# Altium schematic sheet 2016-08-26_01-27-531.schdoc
size 237 x 127 mm; SheetNumber: 1; SheetTotal: 1
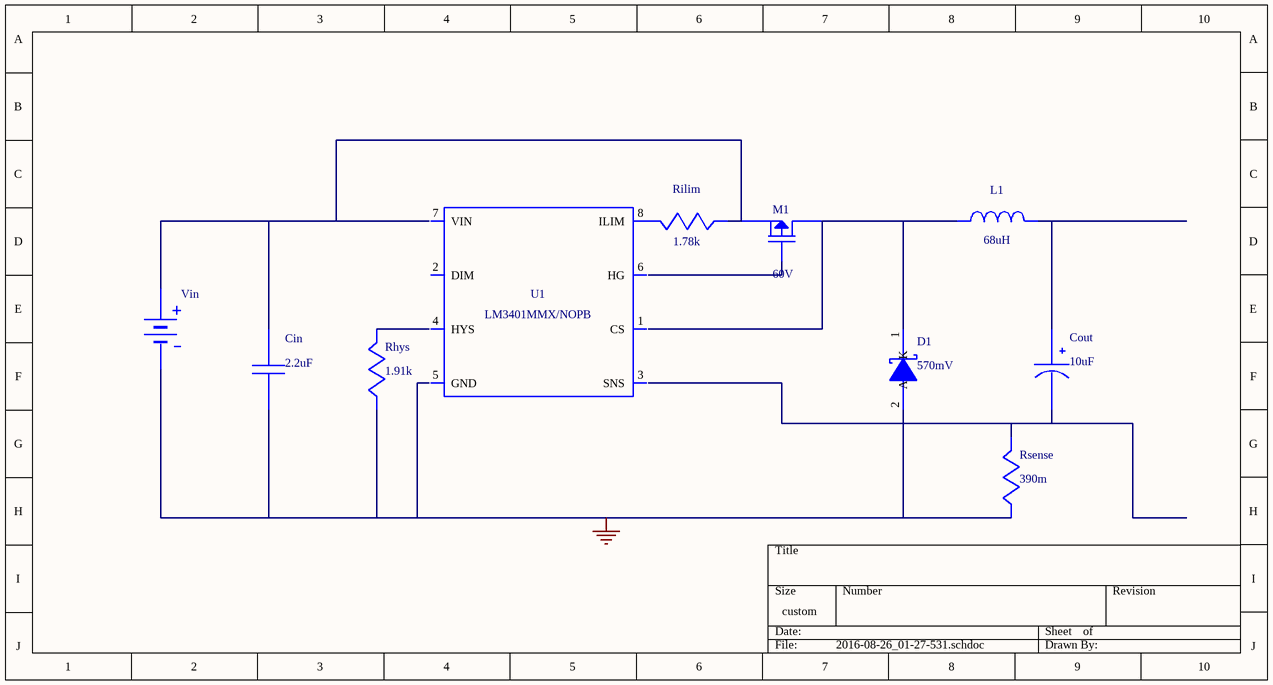
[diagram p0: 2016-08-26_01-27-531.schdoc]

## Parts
Cin  value 2.2uF  (hidden comment: GRM31CR71H225KA88L)
Cout  value 10uF  (hidden comment: UUD1V100MCL1GS)
D1  value 570mV  (hidden comment: PMEG6010CEH,115)
L1  value 68uH  (hidden comment: SRN6045-680M)
M1  value -60V  (hidden comment: FDC5614P)
Rhys  value 1.91k  (hidden comment: ERJ-6ENF1911V)
Rilim  value 1.78k  (hidden comment: ERJ-6ENF1781V)
Rsense  value 390m  (hidden comment: ERJ-8RQFR39V)
U1  LM3401MMX/NOPB
Vin  WB_BATTERY  (value not drawn)

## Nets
0: Cin.2 D1.2(A) Rhys.2 Rsense.2 Vin.2(-)
NetCin_1: Cin.1 M1.4(Source) Rilim.2 Vin.1(+)
NetCout_1: Cout.1(+) L1.2
NetCout_2: Cout.2(-) Rsense.1
NetD1_1: D1.1(K) L1.1 M1.1(Drain) M1.2(Drain) M1.5(Drain) M1.6(Drain)
NetRilim_1: Rilim.1 U1.8(ILIM)

Not connected (* = marked no-connect by the designer): M1 3(Gate); Rhys 1; U1 1(CS) 2(DIM) 3(SNS) 4(HYS) 5(GND) 6(HG) 7(VIN)

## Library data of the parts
Cin = GRM31CR71H225KA88L: GRM31CR71H225KA8; Manufacturer Name: MuRata
Cout = UUD1V100MCL1GS: Manufacturer Name: Nichicon
D1 = PMEG6010CEH,115: Manufacturer Name: NXP Semiconductor
L1 = SRN6045-680M: Manufacturer Name: Bourns
M1 = FDC5614P: Manufacturer Name: Fairchild Semiconductor
Rhys = ERJ-6ENF1911V: Manufacturer Name: Panasonic
Rilim = ERJ-6ENF1781V: Manufacturer Name: Panasonic
Rsense = ERJ-8RQFR39V: Manufacturer Name: Panasonic
U1 = LM3401MMX/NOPB: Manufacturer Name: Texas Instruments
